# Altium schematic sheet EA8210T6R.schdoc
size 127 x 101 mm
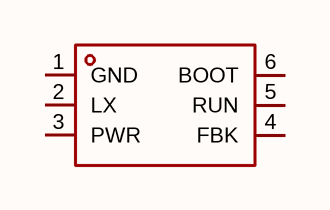
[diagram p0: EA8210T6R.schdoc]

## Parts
U?  ea8210t6r  [SOT-23-6_L2.9-W1.6-P0.95-LS2.8-BL]  (value not drawn)

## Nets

Not connected (* = marked no-connect by the designer): U? 1(GND) 2(LX) 3(PWR) 4(FBK) 5(RUN) 6(BOOT)

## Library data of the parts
U? = ea8210t6r: 功能类型:降压型;工作电压:4.5V~21V;输出电压:600mV~17V;输出电流:2A;输出类型:可调;; Manufacturer: everanalog(申风); AddInBom: yes; ModelId: 18da8f6c14a34920b3e136b5c401a119; ModelName: SOT-23-6_L2.9-W1.6-H1.5-LS2.8-P0.95; ModelTransform: 110.236,113.364,0,90,0,0,0.0005,0.0005,0; Function: 降压型; Output Current: 2A; Frequency - Switching: 500kHz; Synchronous Rectifier: 是; Number of Outputs: 1; Topology: 降压式; Quiescent Current: 600uA; Switch tube (built-in/external): 内置; Output Type: 可调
